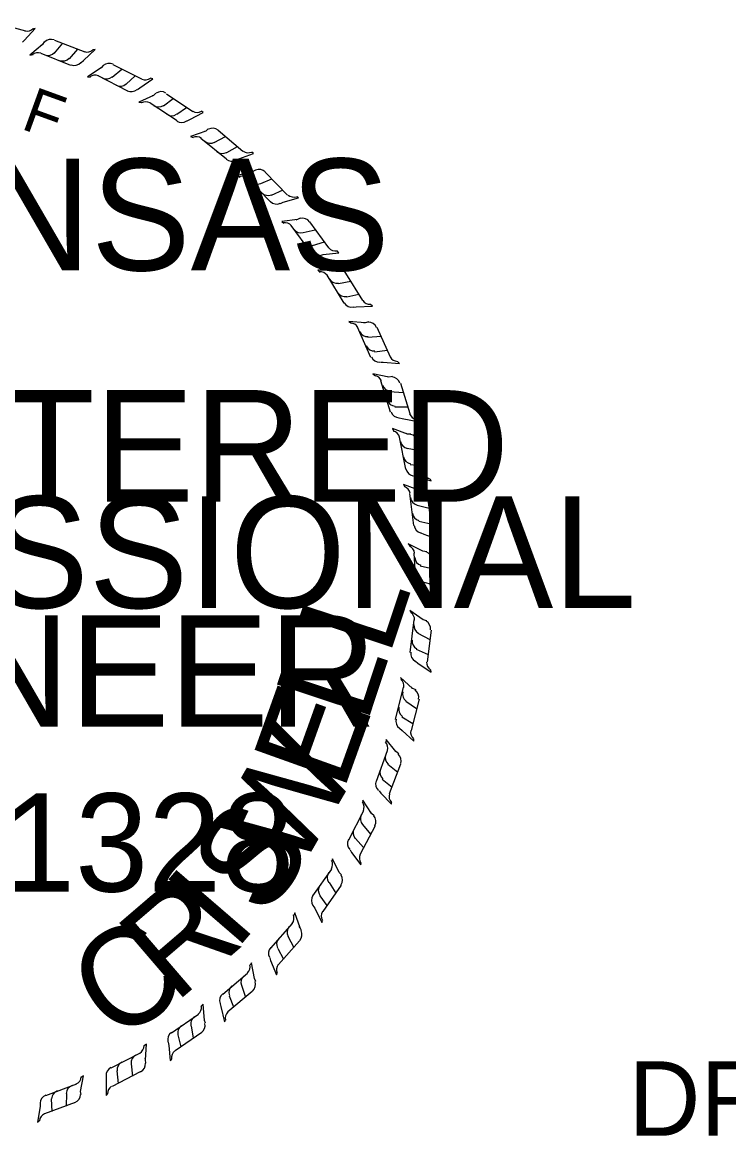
# Model space of a CAD drawing. Extents: x -1771525.8 to -1771491.7, y -422628.7 to -422606.9.
# Drawn here: x -1771499.911 to -1771498.725, y -422627.31 to -422625.44 of the extents above; entities that cross this region are included whole.
import ezdxf

# ---------------------------------------------------------------- set-up
doc = ezdxf.new("R2010")
doc.units = 0
doc.layers.add('Border 2660-Hwy18 - Stamp-ChrisC', color=7, linetype='Continuous')
doc.layers.add('Border 2660-Hwy18 - Text', color=7, linetype='Continuous')

msp = doc.modelspace()

# ---------------------------------------------------------------- linework, layer by layer
at = {"layer": 'Border 2660-Hwy18 - Stamp-ChrisC'}
for p, q in [((-1771499.9585, -422625.44), (-1771499.906, -422625.4542)), ((-1771499.9075, -422625.47), (-1771499.8895, -422625.4505)), ((-1771499.8895, -422625.4505), (-1771499.8925, -422625.4512)), ((-1771499.9112, -422625.4737), (-1771499.9075, -422625.47)), ((-1771499.8775, -422625.4775), (-1771499.8985, -422625.4955)), ((-1771499.8775, -422625.4775), (-1771499.879, -422625.479)), ((-1771499.8745, -422625.473), (-1771499.8775, -422625.4775)), ((-1771499.8572, -422625.47), (-1771499.8062, -422625.4895)), ((-1771499.8572, -422625.4917), (-1771499.843, -422625.4752)), ((-1771499.8317, -422625.5015), (-1771499.8182, -422625.485)), ((-1771499.8985, -422625.4955), (-1771499.8932, -422625.494)), ((-1771499.8295, -422625.5127), (-1771499.8797, -422625.4925)), ((-1771499.8085, -422625.5045), (-1771499.789, -422625.4857)), ((-1771499.789, -422625.4857), (-1771499.7927, -422625.4865)), ((-1771499.8122, -422625.5075), (-1771499.8085, -422625.5045)), ((-1771499.7785, -422625.5165), (-1771499.8017, -422625.5315)), ((-1771499.7785, -422625.5165), (-1771499.7815, -422625.518)), ((-1771499.7755, -422625.5127), (-1771499.7785, -422625.5165)), ((-1771499.7605, -422625.5322), (-1771499.744, -422625.5187)), ((-1771499.759, -422625.5112), (-1771499.711, -422625.5352)), ((-1771499.8017, -422625.5315), (-1771499.7965, -422625.5322)), ((-1771499.7342, -422625.5555), (-1771499.7837, -422625.53)), ((-1771499.7365, -422625.5442), (-1771499.7215, -422625.53)), ((-1771499.714, -422625.5502), (-1771499.6922, -422625.5352)), ((-1771499.6922, -422625.5352), (-1771499.696, -422625.5337)), ((-1771499.7177, -422625.5532), (-1771499.714, -422625.5502)), ((-1771499.687, -422625.5592), (-1771499.6907, -422625.563)), ((-1771499.669, -422625.56), (-1771499.6247, -422625.59)), ((-1771499.6907, -422625.563), (-1771499.7155, -422625.5742)), ((-1771499.7155, -422625.5742), (-1771499.711, -422625.575)), ((-1771499.651, -422625.6057), (-1771499.6967, -422625.5757)), ((-1771499.6907, -422625.563), (-1771499.693, -422625.5637)), ((-1771499.6742, -422625.5802), (-1771499.6577, -422625.5682)), ((-1771499.6517, -422625.5945), (-1771499.6352, -422625.5832)), ((-1771499.63, -422625.6035), (-1771499.6075, -422625.5915)), ((-1771499.6075, -422625.5915), (-1771499.6105, -422625.5892)), ((-1771499.6345, -422625.6057), (-1771499.63, -422625.6035)), ((-1771499.603, -422625.623), (-1771499.6285, -422625.632)), ((-1771499.6285, -422625.632), (-1771499.624, -422625.6335)), ((-1771499.5685, -422625.6702), (-1771499.6112, -422625.635)), ((-1771499.603, -422625.623), (-1771499.6052, -422625.6237)), ((-1771499.5992, -422625.6192), (-1771499.603, -422625.623)), ((-1771499.5887, -422625.6417), (-1771499.57, -422625.632)), ((-1771499.582, -422625.6215), (-1771499.5407, -422625.6567)), ((-1771499.5677, -422625.659), (-1771499.5497, -422625.6485)), ((-1771499.552, -422625.6717), (-1771499.5475, -422625.6695)), ((-1771499.5475, -422625.6695), (-1771499.5227, -422625.6605)), ((-1771499.5227, -422625.6605), (-1771499.5257, -422625.6582)), ((-1771499.5242, -422625.6905), (-1771499.5497, -422625.6972)), ((-1771499.5242, -422625.6905), (-1771499.5265, -422625.692)), ((-1771499.5197, -422625.6882), (-1771499.5242, -422625.6905)), ((-1771499.5497, -422625.6972), (-1771499.5452, -422625.7002)), ((-1771499.4942, -422625.7415), (-1771499.5332, -422625.7017)), ((-1771499.5107, -422625.7107), (-1771499.492, -422625.7032)), ((-1771499.5032, -422625.692), (-1771499.4657, -422625.7302)), ((-1771499.4927, -422625.7302), (-1771499.4732, -422625.7212)), ((-1771499.4777, -422625.7445), (-1771499.4732, -422625.7422)), ((-1771499.4732, -422625.7422), (-1771499.447, -422625.7347)), ((-1771499.447, -422625.7347), (-1771499.45, -422625.7332)), ((-1771499.4492, -422625.7715), (-1771499.4755, -422625.7745)), ((-1771499.4755, -422625.7745), (-1771499.4717, -422625.7775)), ((-1771499.4267, -422625.8262), (-1771499.4597, -422625.7812)), ((-1771499.4492, -422625.7715), (-1771499.4515, -422625.7722)), ((-1771499.4447, -422625.7692), (-1771499.4492, -422625.7715)), ((-1771499.429, -422625.7752), (-1771499.3967, -422625.8187)), ((-1771499.4395, -422625.7932), (-1771499.4192, -422625.7887)), ((-1771499.4237, -422625.815), (-1771499.4035, -422625.809)), ((-1771499.411, -422625.8315), (-1771499.4057, -422625.83)), ((-1771499.4057, -422625.83), (-1771499.3795, -422625.827)), ((-1771499.3795, -422625.827), (-1771499.3825, -422625.824)), ((-1771499.3877, -422625.8562), (-1771499.4147, -422625.8562)), ((-1771499.4147, -422625.8562), (-1771499.411, -422625.86)), ((-1771499.3877, -422625.8562), (-1771499.3907, -422625.8555)), ((-1771499.3832, -422625.854), (-1771499.3877, -422625.8562)), ((-1771499.3705, -422625.9117), (-1771499.399, -422625.8645)), ((-1771499.3802, -422625.8787), (-1771499.3592, -422625.875)), ((-1771499.3682, -422625.8615), (-1771499.3397, -422625.9072)), ((-1771499.366, -422625.9012), (-1771499.3457, -422625.8967)), ((-1771499.3232, -422625.917), (-1771499.3262, -422625.914)), ((-1771499.3547, -422625.9185), (-1771499.3502, -422625.9177)), ((-1771499.3502, -422625.9177), (-1771499.3232, -422625.917)), ((-1771499.3352, -422625.9447), (-1771499.363, -422625.9425)), ((-1771499.363, -422625.9425), (-1771499.3585, -422625.9455)), ((-1771499.3255, -422626.0032), (-1771499.348, -422625.9522)), ((-1771499.3352, -422625.9447), (-1771499.3382, -422625.9447)), ((-1771499.3292, -422625.9432), (-1771499.3352, -422625.9447)), ((-1771499.3157, -422625.9522), (-1771499.2932, -422626.0017)), ((-1771499.3307, -422625.9687), (-1771499.3082, -422625.9672)), ((-1771499.3195, -422625.9935), (-1771499.2977, -422625.9905)), ((-1771499.3097, -422626.0107), (-1771499.3052, -422626.0107)), ((-1771499.3052, -422626.0107), (-1771499.2775, -422626.013)), ((-1771499.2775, -422626.013), (-1771499.2805, -422626.01)), ((-1771499.2955, -422626.0362), (-1771499.3225, -422626.0302)), ((-1771499.3225, -422626.0302), (-1771499.318, -422626.034)), ((-1771499.2925, -422626.0947), (-1771499.309, -422626.0422)), ((-1771499.2955, -422626.0362), (-1771499.2977, -422626.0355)), ((-1771499.2895, -422626.0347), (-1771499.2955, -422626.0362)), ((-1771499.276, -422626.046), (-1771499.2602, -422626.097)), ((-1771499.294, -422626.0602), (-1771499.2715, -422626.0617)), ((-1771499.2857, -422626.0857), (-1771499.264, -422626.0857)), ((-1771499.2782, -422626.1045), (-1771499.273, -422626.1052)), ((-1771499.273, -422626.1052), (-1771499.2467, -422626.1105)), ((-1771499.2467, -422626.1105), (-1771499.249, -422626.1075)), ((-1771499.264, -422626.1315), (-1771499.2895, -422626.1225)), ((-1771499.2895, -422626.1225), (-1771499.2872, -422626.127)), ((-1771499.267, -422626.1907), (-1771499.2775, -422626.1367)), ((-1771499.264, -422626.1315), (-1771499.2662, -422626.1307)), ((-1771499.2587, -422626.1315), (-1771499.264, -422626.1315)), ((-1771499.2647, -422626.1555), (-1771499.2437, -422626.1592)), ((-1771499.2467, -422626.145), (-1771499.2362, -422626.1975)), ((-1771499.2595, -422626.1825), (-1771499.2385, -422626.1847)), ((-1771499.2542, -422626.202), (-1771499.2497, -422626.2035)), ((-1771499.2497, -422626.2035), (-1771499.2242, -422626.2102)), ((-1771499.2242, -422626.2102), (-1771499.2257, -422626.208)), ((-1771499.2452, -422626.226), (-1771499.2707, -422626.2162)), ((-1771499.2707, -422626.2162), (-1771499.2685, -422626.22)), ((-1771499.2535, -422626.2852), (-1771499.2602, -422626.2312)), ((-1771499.2452, -422626.226), (-1771499.2482, -422626.226)), ((-1771499.24, -422626.2267), (-1771499.2452, -422626.226)), ((-1771499.2482, -422626.2507), (-1771499.228, -422626.256)), ((-1771499.2302, -422626.241), (-1771499.2235, -422626.295)), ((-1771499.2452, -422626.2777), (-1771499.225, -422626.2822)), ((-1771499.2415, -422626.2972), (-1771499.237, -422626.2995)), ((-1771499.237, -422626.2995), (-1771499.2122, -422626.3085)), ((-1771499.2122, -422626.3085), (-1771499.213, -422626.3055)), ((-1771499.2385, -422626.328), (-1771499.2632, -422626.316)), ((-1771499.2632, -422626.316), (-1771499.2595, -422626.3197)), ((-1771499.2497, -422626.3865), (-1771499.2527, -422626.3317)), ((-1771499.2385, -422626.328), (-1771499.2407, -422626.3272)), ((-1771499.2317, -422626.3295), (-1771499.2385, -422626.328)), ((-1771499.222, -422626.3437), (-1771499.2182, -422626.3977)), ((-1771499.243, -422626.3527), (-1771499.2205, -422626.358)), ((-1771499.2407, -422626.379), (-1771499.2197, -422626.385)), ((-1771499.2385, -422626.3992), (-1771499.234, -422626.4015)), ((-1771499.234, -422626.4015), (-1771499.2092, -422626.412)), ((-1771499.2092, -422626.412), (-1771499.2107, -422626.409)), ((-1771499.2377, -422626.4435), (-1771499.2602, -422626.4277)), ((-1771499.2602, -422626.4277), (-1771499.2572, -422626.4322)), ((-1771499.2595, -422626.4982), (-1771499.2527, -422626.4435)), ((-1771499.2377, -422626.4435), (-1771499.24, -422626.442)), ((-1771499.2317, -422626.445), (-1771499.2377, -422626.4435)), ((-1771499.2467, -422626.466), (-1771499.2265, -422626.4765)), ((-1771499.2242, -422626.4607), (-1771499.231, -422626.514)), ((-1771499.2497, -422626.493), (-1771499.2295, -422626.502)), ((-1771499.2505, -422626.5132), (-1771499.2467, -422626.5162)), ((-1771499.2467, -422626.5162), (-1771499.2242, -422626.5312)), ((-1771499.2242, -422626.5312), (-1771499.225, -422626.5275)), ((-1771499.2557, -422626.559), (-1771499.276, -422626.5402)), ((-1771499.276, -422626.5402), (-1771499.2737, -422626.5447)), ((-1771499.2842, -422626.6107), (-1771499.2707, -422626.5567)), ((-1771499.2557, -422626.559), (-1771499.2572, -422626.5567)), ((-1771499.2497, -422626.5612), (-1771499.2557, -422626.559)), ((-1771499.267, -422626.58), (-1771499.249, -422626.5927)), ((-1771499.2445, -422626.577), (-1771499.258, -422626.6295)), ((-1771499.2737, -422626.6062), (-1771499.255, -422626.6175)), ((-1771499.2775, -422626.6257), (-1771499.273, -422626.6295)), ((-1771499.3, -422626.6445), (-1771499.3007, -422626.649)), ((-1771499.2835, -422626.6647), (-1771499.3, -422626.6445)), ((-1771499.273, -422626.6295), (-1771499.2535, -422626.6475)), ((-1771499.2535, -422626.6475), (-1771499.2535, -422626.6437)), ((-1771499.3165, -422626.7142), (-1771499.2977, -422626.6632)), ((-1771499.2835, -422626.6647), (-1771499.285, -422626.664)), ((-1771499.279, -422626.6685), (-1771499.2835, -422626.6647)), ((-1771499.297, -422626.6857), (-1771499.2805, -422626.6992)), ((-1771499.276, -422626.6857), (-1771499.2947, -422626.736)), ((-1771499.3067, -422626.7112), (-1771499.2902, -422626.7247)), ((-1771499.312, -422626.7307), (-1771499.309, -422626.7345)), ((-1771499.309, -422626.7345), (-1771499.291, -422626.7532)), ((-1771499.339, -422626.7465), (-1771499.3397, -422626.751)), ((-1771499.3247, -422626.769), (-1771499.339, -422626.7465)), ((-1771499.291, -422626.7532), (-1771499.291, -422626.7502)), ((-1771499.363, -422626.8132), (-1771499.3375, -422626.7637)), ((-1771499.3247, -422626.769), (-1771499.3255, -422626.7667)), ((-1771499.3202, -422626.7727), (-1771499.3247, -422626.769)), ((-1771499.3187, -422626.7892), (-1771499.3435, -422626.8372)), ((-1771499.3397, -422626.787), (-1771499.3262, -422626.8035)), ((-1771499.3517, -422626.811), (-1771499.3382, -422626.826)), ((-1771499.3607, -422626.8297), (-1771499.3585, -422626.8342)), ((-1771499.39, -422626.8447), (-1771499.3915, -422626.8492)), ((-1771499.3787, -422626.868), (-1771499.39, -422626.8447)), ((-1771499.3585, -422626.8342), (-1771499.3427, -422626.8552)), ((-1771499.423, -422626.907), (-1771499.3915, -422626.862)), ((-1771499.3787, -422626.868), (-1771499.3802, -422626.8657)), ((-1771499.375, -422626.8717), (-1771499.3787, -422626.868)), ((-1771499.3427, -422626.8552), (-1771499.342, -422626.8515)), ((-1771499.396, -422626.8845), (-1771499.3847, -422626.9025)), ((-1771499.3757, -422626.889), (-1771499.4065, -422626.9332)), ((-1771499.423, -422626.9235), (-1771499.42, -422626.928)), ((-1771499.4117, -422626.907), (-1771499.3997, -422626.9235)), ((-1771499.4537, -422626.9355), (-1771499.4552, -422626.94)), ((-1771499.4447, -422626.961), (-1771499.4537, -422626.9355)), ((-1771499.42, -422626.928), (-1771499.408, -422626.952)), ((-1771499.4935, -422626.9947), (-1771499.4575, -422626.9535)), ((-1771499.4447, -422626.961), (-1771499.4462, -422626.9587)), ((-1771499.4425, -422626.9655), (-1771499.4447, -422626.961)), ((-1771499.408, -422626.952), (-1771499.4072, -422626.9482)), ((-1771499.465, -422626.9745), (-1771499.4552, -422626.994)), ((-1771499.4822, -422626.9955), (-1771499.4725, -422627.0135)), ((-1771499.4455, -422626.9827), (-1771499.4807, -422627.0225)), ((-1771499.4957, -422627.0112), (-1771499.4942, -422627.0157)), ((-1771499.4942, -422627.0157), (-1771499.4845, -422627.0397)), ((-1771499.5745, -422627.072), (-1771499.5332, -422627.0367)), ((-1771499.5265, -422627.0195), (-1771499.5287, -422627.0232)), ((-1771499.5212, -422627.0457), (-1771499.5265, -422627.0195)), ((-1771499.4845, -422627.0397), (-1771499.483, -422627.0375)), ((-1771499.5212, -422627.0457), (-1771499.522, -422627.0435)), ((-1771499.519, -422627.051), (-1771499.5212, -422627.0457)), ((-1771499.525, -422627.0675), (-1771499.5662, -422627.102)), ((-1771499.564, -422627.075), (-1771499.5565, -422627.0937)), ((-1771499.543, -422627.057), (-1771499.5362, -422627.0772)), ((-1771499.6075, -422627.0892), (-1771499.6112, -422627.093)), ((-1771499.6052, -422627.1162), (-1771499.6075, -422627.0892)), ((-1771499.579, -422627.0885), (-1771499.5775, -422627.093)), ((-1771499.5775, -422627.093), (-1771499.5715, -422627.1185)), ((-1771499.6607, -422627.1372), (-1771499.615, -422627.1057)), ((-1771499.6277, -422627.126), (-1771499.624, -422627.1455)), ((-1771499.6052, -422627.1162), (-1771499.6052, -422627.1132)), ((-1771499.6037, -422627.1207), (-1771499.6052, -422627.1162)), ((-1771499.5715, -422627.1185), (-1771499.57, -422627.1162)), ((-1771499.6097, -422627.1365), (-1771499.6547, -422627.1672)), ((-1771499.6502, -422627.1402), (-1771499.645, -422627.1605)), ((-1771499.7027, -422627.156), (-1771499.7065, -422627.159)), ((-1771499.7042, -422627.1822), (-1771499.7027, -422627.156)), ((-1771499.666, -422627.153), (-1771499.6652, -422627.1582)), ((-1771499.6652, -422627.1582), (-1771499.663, -422627.1837)), ((-1771499.762, -422627.1957), (-1771499.714, -422627.171)), ((-1771499.7042, -422627.1822), (-1771499.705, -422627.18)), ((-1771499.7035, -422627.1882), (-1771499.7042, -422627.1822)), ((-1771499.663, -422627.1837), (-1771499.66, -422627.1815)), ((-1771499.7132, -422627.2025), (-1771499.7605, -422627.2272)), ((-1771499.7522, -422627.201), (-1771499.75, -422627.222)), ((-1771499.7282, -422627.189), (-1771499.726, -422627.21)), ((-1771499.8715, -422627.2422), (-1771499.8197, -422627.2227)), ((-1771499.8137, -422627.2355), (-1771499.8085, -422627.2092)), ((-1771499.8085, -422627.2092), (-1771499.8122, -422627.2122)), ((-1771499.7702, -422627.2107), (-1771499.7702, -422627.216)), ((-1771499.7702, -422627.216), (-1771499.7702, -422627.2422)), ((-1771499.837, -422627.2392), (-1771499.8377, -422627.2602)), ((-1771499.8137, -422627.2355), (-1771499.813, -422627.2325)), ((-1771499.8122, -422627.2407), (-1771499.8137, -422627.2355)), ((-1771499.7702, -422627.2422), (-1771499.768, -422627.24)), ((-1771499.8812, -422627.261), (-1771499.8857, -422627.2872)), ((-1771499.8812, -422627.2557), (-1771499.8812, -422627.261)), ((-1771499.8227, -422627.2542), (-1771499.8737, -422627.273)), ((-1771499.8625, -422627.2482), (-1771499.8617, -422627.2692)), ((-1771499.8857, -422627.2872), (-1771499.8827, -422627.285))]:
    msp.add_line(p, q, dxfattribs=at)
for centre, start, end in [((-1771499.9038, -422625.4402), 258.2517, 317.0395), ((-1771499.8629, -422625.4836), 69.0955, 137.4695), ((-1771499.8843, -422625.5059), 73.3563, 132.1441), ((-1771499.8679, -422625.4808), 249.0955, 317.4695), ((-1771499.8432, -422625.4903), 249.0955, 317.4695), ((-1771499.8027, -422625.4752), 253.3563, 312.1441), ((-1771499.824, -422625.4976), 249.0955, 317.4695), ((-1771499.7655, -422625.5238), 63.0708, 131.4448), ((-1771499.7891, -422625.5437), 67.3316, 126.1194), ((-1771499.7702, -422625.5204), 243.0708, 311.4448), ((-1771499.7047, -422625.5218), 247.3316, 306.1194), ((-1771499.7467, -422625.5325), 243.0708, 311.4448), ((-1771499.7283, -422625.5417), 243.0708, 311.4448), ((-1771499.6782, -422625.5713), 56.1736, 124.5476), ((-1771499.704, -422625.5883), 60.4344, 119.2222), ((-1771499.6825, -422625.5674), 236.1736, 304.5476), ((-1771499.6605, -422625.5822), 236.1736, 304.5476), ((-1771499.6176, -422625.5766), 240.4344, 299.2222), ((-1771499.6435, -422625.5936), 236.1736, 304.5476), ((-1771499.619, -422625.647), 54.451, 113.2388), ((-1771499.5916, -422625.6328), 50.1902, 118.5642), ((-1771499.5954, -422625.6284), 230.1902, 298.5642), ((-1771499.5752, -422625.6455), 230.1902, 298.5642), ((-1771499.5594, -422625.6585), 230.1902, 298.5642), ((-1771499.5319, -422625.6443), 234.451, 293.2388), ((-1771499.5135, -422625.7019), 44.9655, 113.3394), ((-1771499.5422, -422625.7135), 49.2262, 108.0141), ((-1771499.517, -422625.6972), 224.9655, 293.3394), ((-1771499.4984, -422625.716), 224.9655, 293.3394), ((-1771499.4838, -422625.7305), 224.9655, 293.3394), ((-1771499.4552, -422625.7189), 229.2262, 288.0141), ((-1771499.4704, -422625.7914), 40.9505, 99.7383), ((-1771499.4404, -422625.784), 36.6897, 105.0637), ((-1771499.4431, -422625.7789), 216.6897, 285.0637), ((-1771499.4274, -422625.8002), 216.6897, 285.0637), ((-1771499.3851, -422625.8092), 220.9505, 279.7383), ((-1771499.4151, -422625.8166), 216.6897, 285.0637), ((-1771499.411, -422625.8737), 36.0034, 94.7913), ((-1771499.3804, -422625.8689), 31.7427, 100.1166), ((-1771499.3827, -422625.8636), 211.7427, 280.1166), ((-1771499.3689, -422625.8861), 211.7427, 280.1166), ((-1771499.358, -422625.9036), 211.7427, 280.1166), ((-1771499.3275, -422625.8988), 216.0034, 274.7913), ((-1771499.3603, -422625.9598), 29.1451, 87.9329), ((-1771499.3294, -422625.9587), 24.8843, 93.2583), ((-1771499.3311, -422625.9532), 204.8843, 273.2583), ((-1771499.32, -422625.9772), 204.8843, 273.2583), ((-1771499.3113, -422625.9958), 204.8843, 273.2583), ((-1771499.2805, -422625.9947), 209.1451, 267.9329), ((-1771499.3218, -422626.0478), 22.0938, 80.8817), ((-1771499.2911, -422626.0505), 17.8331, 86.207), ((-1771499.292, -422626.0448), 197.8331, 266.207), ((-1771499.284, -422626.07), 197.8331, 266.207), ((-1771499.2776, -422626.0896), 197.8331, 266.207), ((-1771499.2469, -422626.0923), 202.0938, 260.8817), ((-1771499.2917, -422626.1407), 15.7912, 74.579), ((-1771499.2614, -422626.1468), 11.5304, 79.9044), ((-1771499.2617, -422626.141), 191.5304, 259.9044), ((-1771499.2565, -422626.1669), 191.5304, 259.9044), ((-1771499.2524, -422626.187), 191.5304, 259.9044), ((-1771499.222, -422626.1931), 195.7912, 254.579), ((-1771499.2742, -422626.2338), 11.4348, 70.2227), ((-1771499.2445, -422626.2422), 7.174, 75.548), ((-1771499.2444, -422626.2364), 187.174, 255.548), ((-1771499.2412, -422626.2626), 187.174, 255.548), ((-1771499.2385, -422626.283), 187.174, 255.548), ((-1771499.2088, -422626.2913), 191.4348, 250.2227), ((-1771499.2668, -422626.3335), 8.033, 66.8208), ((-1771499.2371, -422626.3379), 183.7722, 252.1462), ((-1771499.2376, -422626.3436), 3.7722, 72.1462), ((-1771499.2355, -422626.3643), 183.7722, 252.1462), ((-1771499.2341, -422626.3848), 183.7722, 252.1462), ((-1771499.2049, -422626.3949), 188.033, 246.8208), ((-1771499.267, -422626.4434), 357.57, 56.3579), ((-1771499.2386, -422626.4531), 173.3093, 241.6832), ((-1771499.2401, -422626.4586), 353.3093, 61.6832), ((-1771499.2417, -422626.4793), 173.3093, 241.6832), ((-1771499.2441, -422626.4997), 173.3093, 241.6832), ((-1771499.2172, -422626.515), 177.57, 236.3579), ((-1771499.2848, -422626.5548), 350.445, 49.2329), ((-1771499.2578, -422626.568), 166.1842, 234.5582), ((-1771499.26, -422626.5733), 346.1842, 54.5582), ((-1771499.2642, -422626.5936), 166.1842, 234.5582), ((-1771499.269, -422626.6136), 166.1842, 234.5582), ((-1771499.2442, -422626.632), 170.445, 229.2329), ((-1771499.3121, -422626.6589), 344.1611, 42.9489), ((-1771499.2868, -422626.6749), 159.9003, 228.2743), ((-1771499.2895, -422626.6799), 339.9003, 48.2743), ((-1771499.2959, -422626.6997), 159.9003, 228.2743), ((-1771499.3029, -422626.719), 159.9003, 228.2743), ((-1771499.2803, -422626.74), 164.1611, 222.9489), ((-1771499.3519, -422626.7586), 337.1149, 35.9028), ((-1771499.3287, -422626.7776), 152.8541, 221.2281), ((-1771499.332, -422626.7823), 332.8541, 41.2281), ((-1771499.3408, -422626.801), 152.8541, 221.2281), ((-1771499.3501, -422626.8193), 152.8541, 221.2281), ((-1771499.4048, -422626.8545), 329.7262, 28.514), ((-1771499.3303, -422626.843), 157.1149, 215.9028), ((-1771499.3842, -422626.8763), 145.4654, 213.8394), ((-1771499.3881, -422626.8805), 325.4654, 33.8394), ((-1771499.4108, -422626.915), 145.4654, 213.8394), ((-1771499.3992, -422626.898), 145.4654, 213.8394), ((-1771499.4696, -422626.9443), 322.7822, 21.57), ((-1771499.3942, -422626.941), 149.7262, 208.514), ((-1771499.4517, -422626.9684), 138.5214, 206.8953), ((-1771499.4693, -422626.9882), 138.5214, 206.8953), ((-1771499.4562, -422626.9721), 318.5214, 26.8953), ((-1771499.4829, -422627.0036), 138.5214, 206.8953), ((-1771499.5435, -422627.0261), 314.7826, 13.5704), ((-1771499.4695, -422627.0315), 142.7822, 201.57), ((-1771499.5292, -422627.0525), 130.5218, 198.8958), ((-1771499.5341, -422627.0556), 310.5218, 18.8958), ((-1771499.565, -422627.083), 130.5218, 198.8958), ((-1771499.5494, -422627.0696), 130.5218, 198.8958), ((-1771499.6251, -422627.0943), 308.9134, 7.7012), ((-1771499.6136, -422627.122), 124.6526, 193.0266), ((-1771499.5556, -422627.1125), 134.7826, 193.5704), ((-1771499.6354, -422627.137), 124.6526, 193.0266), ((-1771499.6188, -422627.1246), 304.6526, 13.0266), ((-1771499.6523, -422627.1487), 124.6526, 193.0266), ((-1771499.7214, -422627.1585), 301.0994, 359.8872), ((-1771499.6459, -422627.179), 128.9134, 187.7013), ((-1771499.7374, -422627.1994), 116.8386, 185.2126), ((-1771499.7137, -422627.1876), 116.8386, 185.2126), ((-1771499.7557, -422627.2087), 116.8386, 185.2126), ((-1771499.7192, -422627.1894), 296.8386, 5.2126), ((-1771499.8268, -422627.2095), 294.7331, 353.521), ((-1771499.8665, -422627.2556), 110.4724, 178.8463), ((-1771499.8473, -422627.2484), 110.4724, 178.8463), ((-1771499.8225, -422627.2392), 110.4724, 178.8463), ((-1771499.8281, -422627.2404), 290.4724, 358.8463), ((-1771499.7535, -422627.2396), 121.0994, 179.8872), ((-1771499.8678, -422627.2865), 114.7331, 173.521)]:
    msp.add_arc(centre, 0.0148, start, end, dxfattribs=at)

# ---------------------------------------------------------------- texts
for s, height, rotation, p in [('F', 0.075, 340.0707, (-1771499.9155, -422625.6182)), ('L', 0.1642, 71.6828, (-1771499.2954, -422626.507)), ('L', 0.1642, 71.6828, (-1771499.3331, -422626.6208)), ('E', 0.1642, 70.3031, (-1771499.3725, -422626.7341)), ('W', 0.1642, 60.0948, (-1771499.4484, -422626.8722)), ('S', 0.1642, 53.9956, (-1771499.5051, -422626.9475)), ('I', 0.1642, 49.2381, (-1771499.5546, -422627.0018)), ('R', 0.1642, 40.6231, (-1771499.6552, -422627.089)), ('C', 0.1642, 32.5951, (-1771499.7596, -422627.1558))]:
    msp.add_text(s, height=height, rotation=rotation, dxfattribs=at).set_placement(p)
for s, height, p in [('ARKANSAS', 0.1875, (-1771500.6595, -422625.8567)), ('REGISTERED', 0.1875, (-1771500.7232, -422626.2452)), ('PROFESSIONAL', 0.187497, (-1771500.8305, -422626.4237)), ('ENGINEER', 0.1875, (-1771500.6257, -422626.6232)), ('No. 11328', 0.165, (-1771500.4726, -422626.8999))]:
    msp.add_text(s, height=height, dxfattribs=at).set_placement(p)
at = {"layer": 'Border 2660-Hwy18 - Text'}
msp.add_text('DRAWN BY:', height=0.125, dxfattribs=at).set_placement((-1771498.8929, -422627.3099))

doc.saveas('drawing.dxf')
